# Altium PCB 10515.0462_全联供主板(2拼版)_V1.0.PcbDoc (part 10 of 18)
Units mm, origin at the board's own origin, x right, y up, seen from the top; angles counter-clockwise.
Board outline 282 x 198 mm, 2 copper layers (Top Layer, Bottom Layer); 716 components, 0 nets, 2364 pads, 1800 vias.
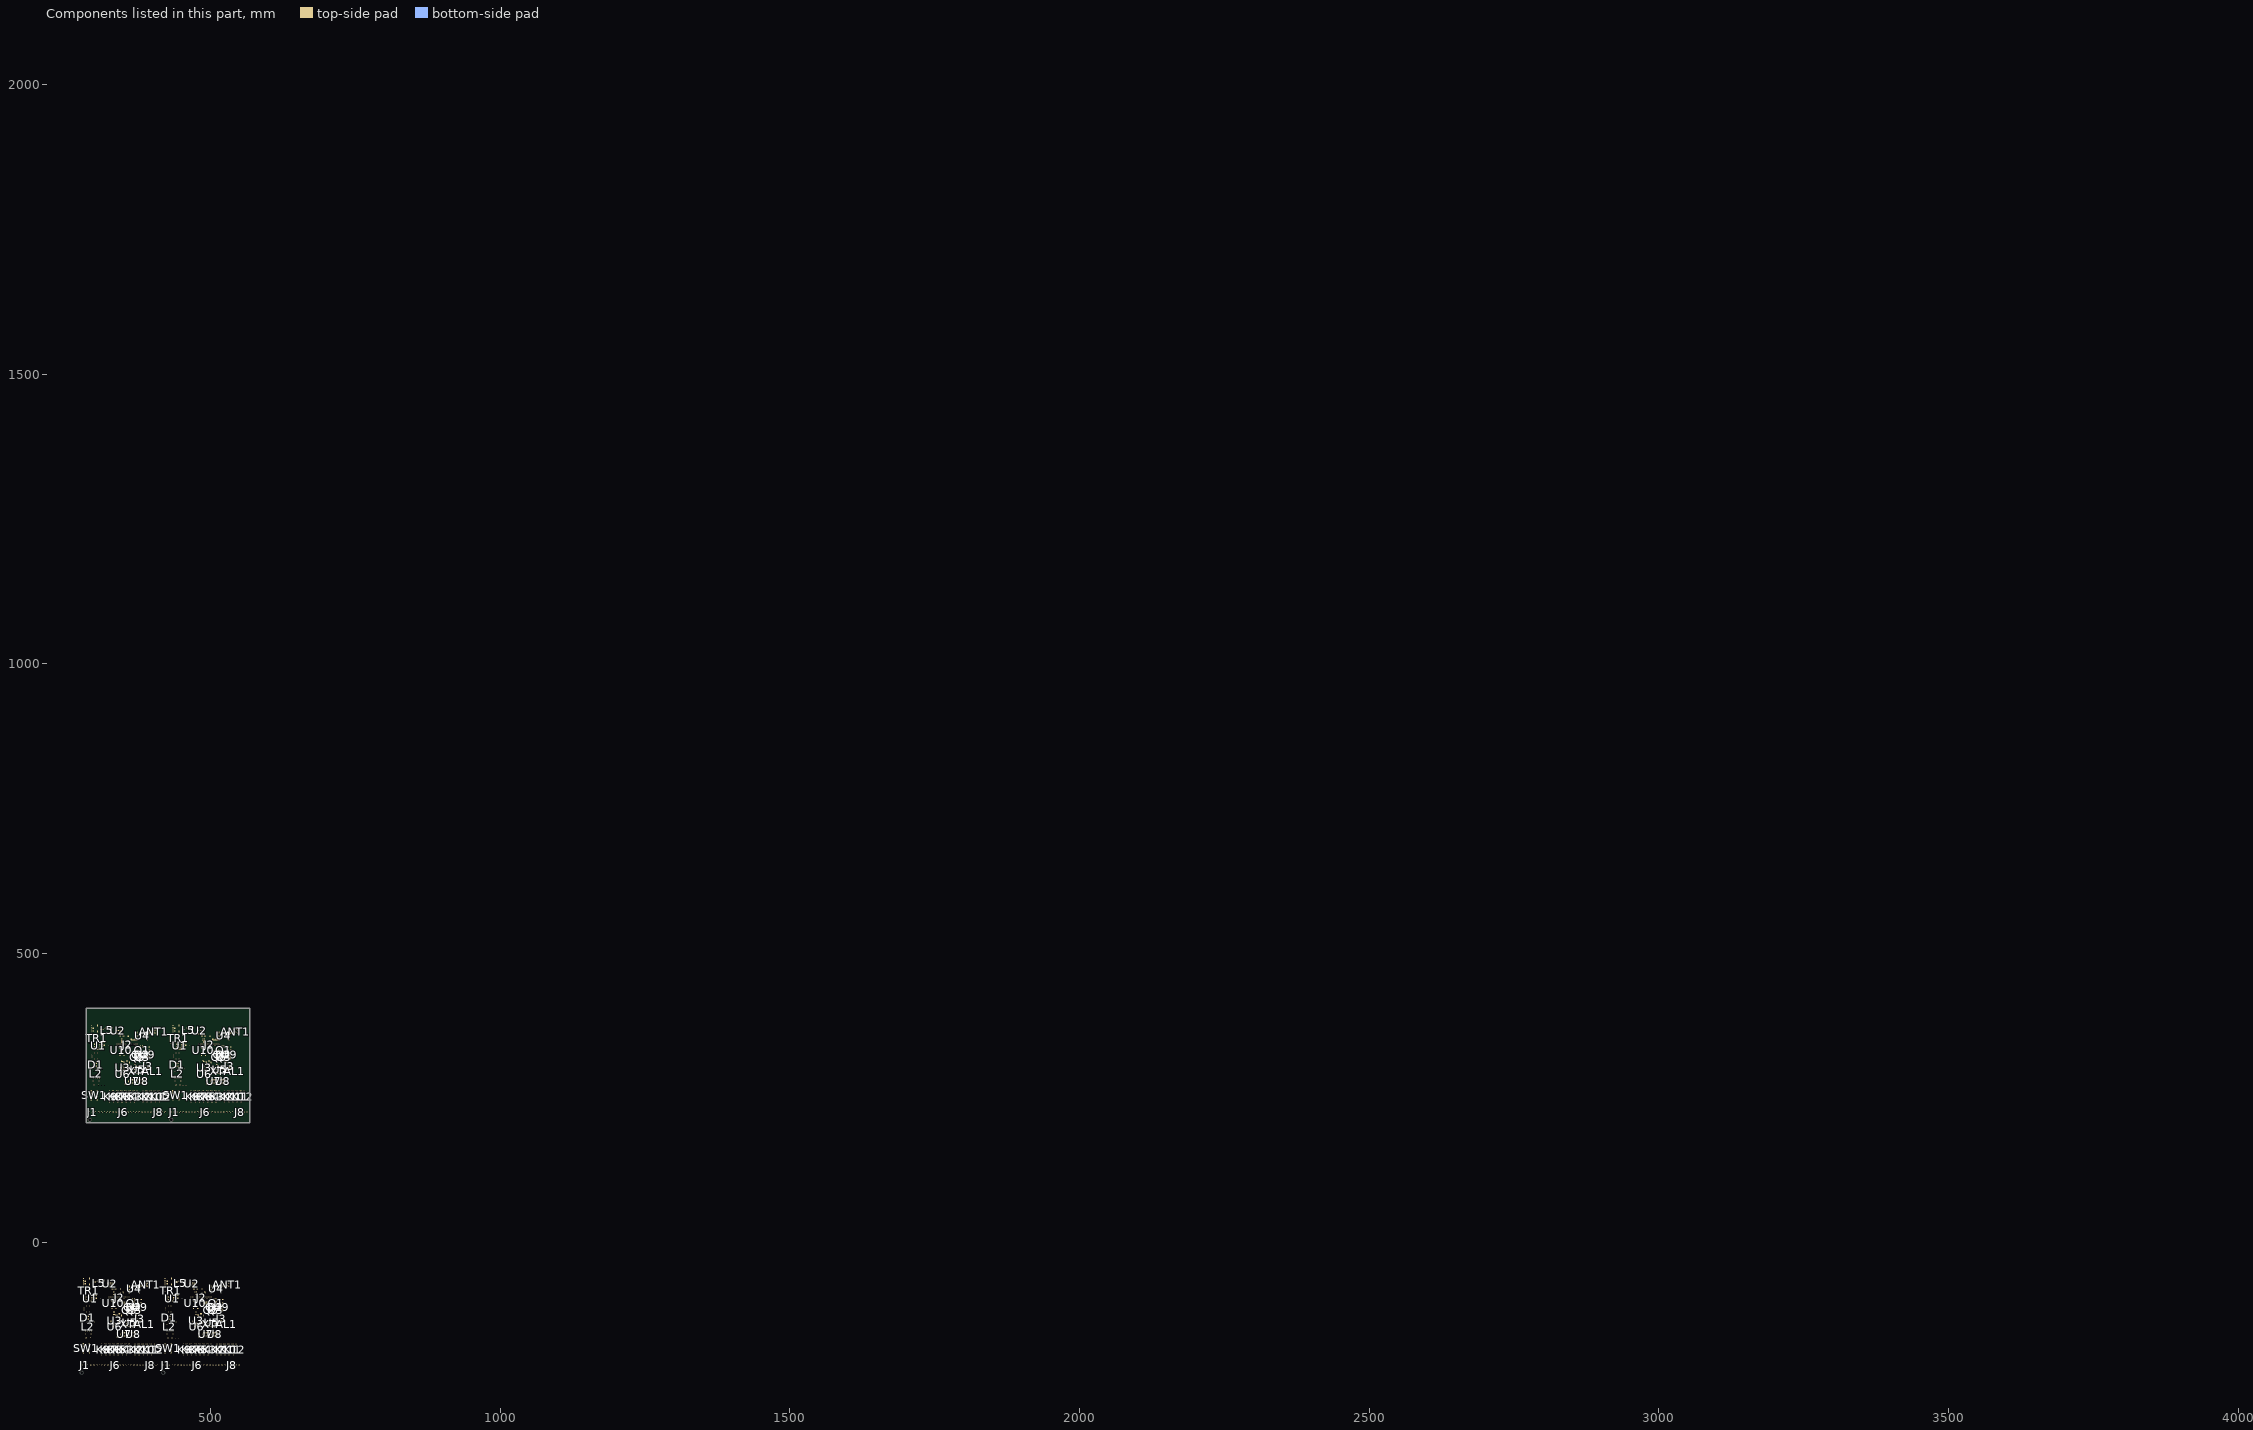
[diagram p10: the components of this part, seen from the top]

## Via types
v1: diameter 0.7, hole 0.4, Top Layer to Bottom Layer, tented both sides, 1800 vias

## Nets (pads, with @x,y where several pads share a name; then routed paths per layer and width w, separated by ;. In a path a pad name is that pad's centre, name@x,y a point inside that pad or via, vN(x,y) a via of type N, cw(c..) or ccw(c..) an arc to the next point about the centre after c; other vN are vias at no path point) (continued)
copper on no net: (continued)
  Top Layer w0.65: 372.479,328.689 cw(c371.859,328.069) 372.735,328.069 ; 372.735,317.501 cw(c374.744,317.501) 373.733,319.236 ; 372.735,317.686 372.735,318.663 373.577,319.504 ; 372.735,318.314 cw(c373.616,318.314) 373.587,319.194 ; 372.735,318.632 cw(c374.085,318.632) 373.406,319.798 ; 372.735,318.986 cw(c373.594,318.986) 373.566,319.844 ; 372.735,326.83 372.735,328.945 ; 372.735,327.857 cw(c373.911,327.857) 373.08,328.689 ; 372.76,322.137 v1(372.76,324.555) 372.76,325.393 ; v1(372.772,331.039) 372.772,332.937 ; 373.267,319.504 cw(c372.518,319.504) 373.048,318.975 cw(c373.577,318.446) 373.577,319.194 ; v1(373.614,-112.057) 374.453,-112.057 379.78,-112.057 380.616,-112.057 381.361,-112.802 381.361,-119.533 v1(381.615,-119.787) ; 374.386,317.686 376.545,317.686 376.545,316.965 376.956,316.554 v1(377.21,316.554) ; 374.386,326.83 374.386,323.814 374.577,323.624 374.577,322.004 ; 374.389,323.735 cw(c373.935,323.281) 374.577,323.281 ; 374.402,322.242 ccw(c373.982,322.663) 374.577,322.663 ccw(c375.172,322.663) 374.751,322.242 ; v1(375.457,-119.787) 375.457,-118.864 ; 375.908,329.29 ccw(c375.182,330.015) 376.208,330.015 ccw(c377.234,330.015) 376.509,329.29 ccw(c377.234,330.015) 377.234,328.989 ccw(c377.234,327.963) 376.509,328.689 ; 376.307,323.798 cw(c375.887,323.377) 376.482,323.377 cw(c377.077,323.377) 376.656,323.798 ; 376.359,331.324 cw(c377.972,329.711) 377.972,331.992 ; 376.482,322.068 376.482,324.036 ; 376.734,316.777 ccw(c377.21,317.253) v1@377.21,316.579 ; 377.003,-73.91 374.279,-73.91 373.36,-74.829 373.36,-83.465 372.695,-84.13 359.303,-84.13 357.866,-84.13 ; v1@377.006,-119.75 377.006,-118.864 ; 377.21,307.789 v1(377.21,309.315) ; 377.263,326.755 ccw(c376.733,327.284) 377.482,327.284 ccw(c378.23,327.284) 377.701,326.755 ; 377.482,326.536 377.482,328.846 ; 377.972,332.937 376.208,331.174 376.208,328.989 378.875,328.989 ; 378.196,319.845 378.196,317.686 380.482,317.686 ; 378.51,-108.253 378.51,-105.753 ; 378.51,-106.121 cw(c379.212,-106.121) 378.715,-105.624 ; 378.575,328.689 ccw(c377.849,327.963) 377.849,328.989 ccw(c377.849,330.015) 378.575,329.29 ; v1(378.92,308.486) 379.736,309.301 v1(379.736,310.331) ; v1(379.75,335.477) 380.829,335.477 ; 380.498,323.798 cw(c380.078,323.377) 380.673,323.377 cw(c381.268,323.377) 380.847,323.798 ; 380.673,324.036 380.673,322.964 381.673,321.964 384.252,321.964 384.356,322.068 ; 380.766,334.556 ccw(c381.641,334.556) 381.022,333.937 ; 380.766,335.477 380.766,333.781 380.848,333.699 ; 381.361,-119.113 ccw(c382.289,-119.113) v1@381.633,-119.769 ; 381.363,321.964 ccw(c380.614,321.964) 381.144,322.493 ccw(c381.673,323.022) 381.673,322.274 ; 381.579,330.98 cw(c379.827,329.229) 382.304,329.229 ; 381.798,331.2 382.304,330.693 382.304,328.989 ; 381.892,321.745 cw(c382.421,321.216) 382.421,321.964 cw(c382.421,322.712) 381.892,322.183 ; 382.004,329.29 ccw(c381.278,330.015) 382.304,330.015 ccw(c383.33,330.015) 382.605,329.29 ; 382.038,331.44 cw(c381.396,330.798) 382.304,330.798 ; 382.461,335.42 cw(c381.647,334.606) 382.798,334.606 ; 382.48,335.477 382.798,335.16 382.798,333.699 ; 382.623,319.464 382.623,319.143 v1(383.433,318.332) ; 382.624,333.937 ccw(c382.203,334.358) 382.798,334.358 ccw(c383.393,334.358) 382.972,333.937 ; v1@382.631,-74.482 385.033,-74.482 ; 382.869,319.401 ccw(c384.087,319.401) v1@383.226,318.539 ; v1@382.909,309.315 v1(382.909,309.442) 382.909,310.417 383.407,310.916 ; v1@382.909,309.396 cw(c384.633,309.396) 383.487,310.684 ; v1(387.243,324.539) 388.082,324.539 393.408,324.539 394.245,324.539 394.99,323.793 394.99,317.062 v1(395.244,316.808) ; v1(389.086,316.808) 389.086,317.731 ; 390.632,362.685 387.908,362.685 386.989,361.766 386.989,353.13 386.324,352.465 372.932,352.465 371.495,352.465 ; v1@390.634,316.846 390.634,317.731 ; 392.138,328.342 392.138,330.843 ; 392.138,330.475 cw(c392.841,330.475) 392.344,330.971 ; 394.99,317.482 ccw(c395.917,317.482) v1@395.262,316.826 ; v1@396.26,362.114 398.661,362.114 ; 426.476,-64.542 428.715,-64.542 431.89,-61.367 431.89,-62.336 436.122,-66.568 436.509,-66.568 ; 431.89,-71.667 431.89,-71.51 433.366,-70.035 ; 432.064,-69.749 433.614,-68.2 438.083,-68.2 437.55,-68.733 433.842,-68.733 433.461,-69.114 ; 432.318,-61.875 436.509,-66.066 437.601,-66.066 ; 432.318,-61.113 437.754,-66.549 437.837,-66.549 437.96,-66.426 ; 432.572,-70.003 433.144,-69.431 ; 433.017,-63.462 433.017,-64.288 ; 433.652,-64.923 433.017,-64.923 ; 434.35,-64.034 436.001,-65.685 437.22,-65.685 438.083,-66.549 ; 434.604,-66.568 434.604,-66.51 433.017,-64.923 ; 435.297,-66.568 433.017,-64.288 ; 436.691,-68.733 ccw(c436.691,-66.845) 438.026,-68.18 ; 436.813,-66.066 cw(c436.813,-67.78) 438.026,-66.568 436.509,-66.568 ; 438.083,-66.429 ccw(c438.083,-65.893) 438.462,-66.272 ; 438.141,-66.568 cw(c439.353,-67.78) 439.353,-66.066 ; 438.16,-68.479 437.208,-69.431 ; 438.164,-66.519 cw(c438.668,-66.573) 438.668,-66.066 ; 439.801,-66.565 ccw(c438.668,-67.601) 438.668,-66.066 ; 439.861,-66.549 439.379,-66.066 438.668,-66.066 ; 440.105,372.053 442.344,372.053 445.519,375.228 445.519,374.259 449.751,370.027 450.138,370.027 ; 440.738,-66.637 cw(c441.203,-67.102) 441.547,-66.542 ; 441.097,-65.669 cw(c442.224,-66.795) v1@442.224,-65.202 ; 441.272,-65.494 cw(c442.023,-66.246) v1@442.219,-65.202 ; 441.532,-66.415 ccw(c440.473,-65.356) v1@441.97,-65.356 ; v1@441.571,-65.195 cw(c440.609,-66.157) 441.97,-66.157 ; 441.589,-66.654 cw(c443.547,-66.654) v1@442.241,-65.196 ; 441.589,-66.391 ccw(c441.589,-65.336) 442.335,-66.082 ; v1@441.594,-65.202 cw(c441.79,-66.246) 442.542,-65.494 ; 441.612,-66.394 cw(c441.82,-65.685) 441.081,-65.685 ; 441.97,-65.851 cw(c442.898,-65.851) v1@442.242,-65.195 ; 441.995,-66.549 ccw(c441.995,-62.838) 444.619,-65.462 cw(c443.467,-64.309) 443.467,-65.939 cw(c443.467,-67.569) 444.619,-66.416 ; v1@442.206,-65.195 cw(c441.551,-65.851) 442.478,-65.851 ; 443.564,-66.549 ccw(c443.564,-64.407) 445.078,-65.921 ; 445.519,364.928 445.519,365.085 446.995,366.561 ; 445.693,366.846 447.242,368.396 451.712,368.396 451.178,367.862 447.471,367.862 447.09,367.481 ; 445.947,374.72 450.138,370.529 451.229,370.529 ; 445.947,375.482 451.382,370.047 451.466,370.047 451.589,370.17 ; 446.201,366.592 446.772,367.164 ; 446.645,373.133 446.645,372.307 ; 447.28,371.672 446.645,371.672 ; 447.979,372.561 449.63,370.91 450.848,370.91 451.712,370.047 ; 448.233,370.027 448.233,370.085 446.645,371.672 ; 448.925,370.027 446.645,372.307 ; 449.494,-66.416 cw(c448.342,-67.569) 449.971,-67.569 cw(c451.601,-67.569) 450.448,-66.416 ; 449.504,-73.001 ccw(c448.457,-71.908) 449.971,-71.908 ccw(c451.485,-71.908) 450.438,-73.001 ; 449.735,-66.571 cw(c449.266,-67.827) 450.606,-67.827 ; 449.962,-65.962 cw(c449.616,-66.89) 450.606,-66.89 ; 449.971,-66.614 cw(c449.971,-69.163) 451.774,-67.361 ; 449.996,-73.486 cw(c451.514,-73.292) 450.432,-72.209 ; 449.998,-72.815 ccw(c450.059,-71.234) 451.178,-72.353 ; 450.281,-72.889 cw(c450.941,-71.613) 449.504,-71.613 ; 450.32,367.862 ccw(c450.32,369.75) 451.654,368.415 ; 450.442,370.529 cw(c450.442,368.815) 451.654,370.027 450.138,370.027 ; 450.606,-67.082 451.368,-67.844 453.4,-67.844 ; 450.635,-66.059 ccw(c452.337,-66.367) 451.114,-67.59 ; 450.641,-73.403 cw(c453.174,-73.079) 451.368,-71.273 ; 450.646,-73.489 cw(c452.107,-73.489) 451.074,-72.456 ; 450.646,-65.939 ccw(c451.356,-65.939) 450.854,-66.441 ; 451.712,370.166 ccw(c451.712,370.702) 452.091,370.323 ; 451.769,370.027 cw(c452.982,368.815) 452.982,370.529 ; 451.789,368.116 450.836,367.164 ; 451.793,370.076 cw(c452.297,370.023) 452.297,370.529 ; 453.43,370.03 ccw(c452.297,368.995) 452.297,370.529 ; 453.49,370.047 453.007,370.529 452.297,370.529 ; 454.035,-68.479 455.813,-66.701 455.813,-66.574 ; 454.035,-67.844 454.035,-67.543 456.655,-64.923 ; 454.162,-67.844 455.813,-66.193 ; 454.257,-67.241 cw(c456.655,-69.64) 456.655,-66.248 ; 454.282,-66.581 cw(c456.655,-68.954) 456.655,-65.598 ; 454.289,-71.781 455.305,-72.797 455.305,-74.448 456.08,-75.223 456.655,-75.223 ; 454.367,369.958 cw(c454.832,369.493) 455.175,370.054 ; 454.393,-67.185 cw(c456.655,-69.447) 456.655,-66.248 ; 454.67,-67.844 453.4,-67.844 ; 454.71,370.91 ccw(c455.449,370.91) 455.241,370.201 ; 454.726,370.927 cw(c455.853,369.8) v1@455.853,371.393 ; 454.9,371.101 cw(c455.652,370.35) v1@455.848,371.394 ; 455.124,-66.882 cw(c456.655,-68.414) 456.655,-66.248 ; 455.16,370.181 ccw(c454.102,371.239) v1@455.599,371.239 ; v1@455.2,371.401 cw(c454.238,370.438) 455.599,370.438 ; 455.218,369.942 cw(c457.175,369.942) v1@455.87,371.4 ; 455.218,370.204 ccw(c455.218,371.259) 455.964,370.513 ; v1@455.223,371.394 cw(c455.419,370.35) 456.17,371.101 ; 455.366,-66.132 cw(c456.655,-67.421) 456.655,-65.598 ; 455.392,-65.471 cw(c456.655,-66.735) 456.655,-64.948 ; 455.432,-72.543 454.67,-71.781 451.749,-71.781 451.178,-72.352 ; 455.503,-66.075 cw(c456.655,-67.228) 456.655,-65.598 ; 455.599,370.745 cw(c456.526,370.745) v1@455.871,371.401 ; 455.624,370.047 ccw(c455.624,373.758) 458.248,371.134 cw(c457.095,372.286) 457.095,370.656 cw(c457.095,369.027) 458.248,370.179 ; 455.663,-66.851 ccw(c454.534,-65.723) 456.13,-65.723 ; 455.813,-74.261 ccw(c456.817,-74.261) 456.107,-74.971 ; 455.813,-72.692 ccw(c458.386,-72.692) 456.567,-74.511 ; 455.813,-72.289 454.797,-71.273 451.368,-71.273 449.971,-72.67 449.971,-73.489 ; 455.813,-71.527 455.051,-70.765 451.114,-70.765 449.971,-71.908 449.971,-73.489 ; 455.813,-71.123 ccw(c459.955,-71.123) 457.026,-74.052 cw(c457.923,-73.156) 456.655,-73.156 cw(c455.388,-73.156) 456.284,-74.052 ; 455.813,-68.123 cw(c458.079,-68.123) 456.923,-66.175 ; 455.813,-67.971 454.924,-68.86 ; 455.813,-67.336 454.67,-68.479 451.368,-68.479 450.606,-67.717 450.606,-66.574 449.971,-65.939 ; 455.813,-66.982 cw(c457.402,-66.982) 456.591,-65.615 ; v1@455.835,371.401 cw(c455.179,370.745) 456.107,370.745 ; 455.881,-66.633 ccw(c455.226,-65.978) 456.138,-65.815 ; 455.94,-64.923 453.527,-67.336 451.749,-67.336 450.352,-65.939 449.971,-65.939 ; 456.284,-75.594 ccw(c455.388,-76.49) 455.388,-75.223 ccw(c455.388,-73.956) 456.284,-74.852 ; 456.321,-75.223 455.318,-75.223 454.924,-74.829 454.924,-73.305 453.972,-72.352 451.178,-72.352 ; 456.325,-74.015 ccw(c454.829,-72.162) 457.21,-72.162 ; 456.465,-73.934 ccw(c455.827,-72.289) 457.591,-72.289 ; 456.578,-74.522 ccw(c457.044,-73.925) 457.579,-74.46 ; 456.655,-65.859 456.655,-64.923 ; 456.7,-74.54 ccw(c456.196,-73.238) 457.591,-73.238 ; 456.734,-74.52 ccw(c455.928,-73.523) 457.21,-73.523 ; 456.935,-75.146 ccw(c456.564,-74.188) 457.591,-74.188 ; 456.978,-74.009 ccw(c457.5,-73.34) 458.099,-73.94 ; 457.026,-66.094 ccw(c457.923,-66.99) 456.655,-66.99 ccw(c455.388,-66.99) 456.284,-66.094 cw(c454.354,-68.024) 457.083,-68.024 ; 457.106,-75.491 cw(c457.578,-75.772) 457.578,-75.223 ; 457.106,-74.955 ccw(c457.578,-74.674) 457.578,-75.223 ; 457.18,-65.723 ccw(c459.162,-65.723) 457.761,-67.125 ; 457.193,370.047 ccw(c457.193,372.189) 458.707,370.674 ; 458.353,-71.527 457.591,-72.289 457.591,-74.575 456.943,-75.223 456.655,-75.223 ; 458.516,-68.733 cw(c458.516,-70.094) v1@459.478,-69.132 ; 458.933,-69.278 ccw(c458.933,-67.609) v1@460.113,-68.789 ; 458.988,-71.527 458.099,-72.416 458.099,-73.94 ; 459.04,-69.278 ccw(c459.04,-68.658) v1@459.478,-69.096 ; 459.274,-68.638 cw(c458.798,-69.114) v1@459.471,-69.114 ; v1@459.514,-69.132 cw(c460.476,-70.094) 460.476,-68.733 ; v1@459.514,-69.096 ccw(c459.952,-68.658) 459.952,-69.278 ; v1@459.517,-69.128 cw(c460.131,-69.554) v1(460.131,-68.807) 459.443,-68.807 457.083,-66.447 ; 459.517,-68.733 cw(c459.517,-70.653) v1@460.875,-69.295 ; v1@460.154,-68.797 ccw(c460.893,-68.47) v1(460.893,-69.278) ; 460.675,-68.733 cw(c460.675,-70.094) v1@461.637,-69.132 ; v1@460.915,-69.29 cw(c461.872,-69.834) 461.872,-68.733 ; v1@461.199,-69.278 ccw(c461.199,-68.658) v1@461.637,-69.096 ; 461.285,-71.527 ccw(c461.285,-69.418) 462.776,-70.909 ; v1@461.673,-69.096 ccw(c462.111,-68.658) 462.111,-69.278 ; 461.909,-72.416 461.655,-72.162 ; 461.909,-71.867 462.834,-70.942 ; 462.1,-68.961 ccw(c462.635,-68.425) 462.815,-69.161 ; 462.157,-70.809 ccw(c462.48,-70.486) 462.78,-70.829 ; 462.29,-70.942 461.859,-70.511 457.464,-70.511 456.655,-71.32 456.655,-72.543 ; 462.417,-69.278 461.872,-68.733 ; 462.753,-72.67 462.753,-72.031 462.249,-71.527 ; 462.834,-70.929 462.834,-70.942 ; 462.834,-69.278 v1(460.893,-69.278) ; 462.847,-70.942 462.834,-70.942 ; 463.123,370.179 cw(c461.97,369.027) 463.6,369.027 cw(c465.229,369.027) 464.077,370.179 ; 463.133,363.594 ccw(c462.086,364.687) 463.6,364.687 ccw(c465.114,364.687) 464.067,363.594 ; 463.364,370.024 cw(c462.894,368.769) 464.235,368.769 ; 463.484,-73.99 463.243,-73.749 ; 463.525,-73.441 462.036,-71.953 462.036,-71.527 ; 463.591,370.633 cw(c463.244,369.705) 464.235,369.705 ; 463.6,369.981 cw(c463.6,367.432) 465.403,369.235 ; 463.625,363.11 cw(c465.143,363.304) 464.061,364.386 ; 463.626,363.781 ccw(c463.688,365.361) 464.806,364.243 ; 463.91,363.706 cw(c464.57,364.983) 463.133,364.983 ; 464.235,369.513 464.997,368.751 467.029,368.751 ; 464.264,370.536 ccw(c465.965,370.228) 464.743,369.006 ; 464.269,363.192 cw(c466.803,363.516) 464.997,365.322 ; 464.275,363.106 cw(c465.735,363.106) 464.703,364.139 ; 464.275,370.656 ccw(c464.985,370.656) 464.483,370.155 ; 465.272,-96.104 cw(c464.526,-96.85) 465.581,-96.85 cw(c466.636,-96.85) 465.89,-96.104 cw(c466.636,-96.85) 466.636,-95.795 cw(c466.636,-94.74) 465.89,-95.486 cw(c466.636,-94.74) 465.581,-94.74 cw(c464.526,-94.74) 465.272,-95.486 ; 465.272,-93.564 cw(c464.526,-94.31) 465.581,-94.31 cw(c466.636,-94.31) 465.89,-93.564 cw(c466.664,-94.338) 466.664,-93.244 ; 465.369,-95.413 ccw(c464.799,-94.387) 465.973,-94.387 ; 465.4,-95.683 cw(c466.821,-96.57) 466.821,-94.895 ; 465.427,-93.664 cw(c465.131,-94.453) 465.973,-94.453 ; 465.43,-93.405 ccw(c466.564,-92.283) 466.564,-93.879 ; 465.468,-95.976 ccw(c465.926,-95.242) 466.538,-95.854 ; 465.592,-93.244 468.11,-93.244 468.121,-93.255 ; 465.812,-95.425 ccw(c466.371,-94.531) 467.116,-95.276 ; 465.89,-92.946 ccw(c466.608,-92.228) 466.608,-93.244 ; 465.892,-92.948 ccw(c468.121,-90.744) 468.121,-93.879 ; 465.952,-96.027 cw(c467.994,-97.303) 467.994,-94.895 465.973,-94.895 ; 465.973,-96.419 467.116,-95.276 ; 465.973,-96.188 465.973,-94.895 ; 465.973,-95.988 cw(c467.116,-96.549) 467.116,-95.276 ; 467.017,-94.895 cw(c467.017,-96.338) 468.312,-95.701 ; 467.038,-93.244 cw(c467.038,-94.338) 467.812,-93.564 cw(c467.066,-94.31) 468.121,-94.31 cw(c469.176,-94.31) 468.43,-93.564 ; 467.094,-93.244 ccw(c467.094,-92.228) 467.812,-92.946 ; 467.379,-93.879 ccw(c467.379,-92.79) 468.301,-93.369 ; 467.664,368.116 469.442,369.894 469.442,370.021 ; 467.664,368.751 467.664,369.052 470.284,371.672 ; 467.685,-95.817 ccw(c467.116,-95.845) 467.116,-95.276 ; 467.729,-95.988 ccw(c465.973,-96.851) 465.973,-94.895 ; 467.751,-93.023 cw(c466.205,-92.054) 466.205,-93.879 468.121,-93.879 ; 467.791,368.751 469.442,370.402 ; 467.812,-96.104 ccw(c467.066,-96.85) 467.066,-95.795 ccw(c467.066,-94.74) 467.812,-95.486 ccw(c467.066,-94.74) 468.121,-94.74 ccw(c469.176,-94.74) 468.43,-95.486 ; 467.885,369.354 cw(c470.284,366.956) 470.284,370.347 ; 467.911,370.015 cw(c470.284,367.642) 470.284,370.997 ; 467.918,364.814 468.934,363.798 468.934,362.147 469.709,361.372 470.284,361.372 ; 468.022,369.411 cw(c470.284,367.149) 470.284,370.347 ; 468.121,-95.276 467.116,-95.276 ; 468.121,-94.387 465.973,-94.387 ; 468.299,368.751 467.029,368.751 ; 468.753,369.713 cw(c470.284,368.182) 470.284,370.347 ; 468.995,370.464 cw(c470.284,369.175) 470.284,370.997 ; 469.021,371.124 cw(c470.284,369.861) 470.284,371.647 ; 469.061,364.052 468.299,364.814 465.378,364.814 464.806,364.243 ; 469.132,370.52 cw(c470.284,369.368) 470.284,370.997 ; 469.291,369.744 ccw(c468.163,370.872) 469.759,370.872 ; 469.442,362.334 ccw(c470.446,362.334) 469.736,361.624 ; 469.442,363.903 ccw(c472.015,363.903) 470.195,362.084 ; 469.442,364.306 468.426,365.322 464.997,365.322 463.6,363.925 463.6,363.106 ; 469.442,365.068 468.68,365.83 464.743,365.83 463.6,364.687 463.6,363.106 ; 469.442,365.473 ccw(c473.584,365.473) 470.655,362.544 cw(c471.551,363.44) 470.284,363.44 cw(c469.016,363.44) 469.913,362.544 ; 469.442,368.472 cw(c471.708,368.472) 470.552,370.421 ; 469.442,368.624 468.553,367.735 ; 469.442,369.259 468.299,368.116 464.997,368.116 464.235,368.878 464.235,370.021 463.6,370.656 ; 469.442,369.613 cw(c471.031,369.613) 470.22,370.98 ; 469.51,369.963 ccw(c468.855,370.618) 469.767,370.78 ; 469.569,371.672 467.156,369.259 465.378,369.259 463.981,370.656 463.6,370.656 ; 469.913,361.001 ccw(c469.016,360.105) 469.016,361.372 ccw(c469.016,362.64) 469.913,361.744 ; 469.95,361.372 468.947,361.372 468.553,361.766 468.553,363.29 467.6,364.243 464.806,364.243 ; 469.954,362.581 ccw(c468.457,364.433) 470.839,364.433 ; 470.094,362.662 ccw(c469.456,364.306) 471.22,364.306 ; 470.207,362.074 ccw(c470.673,362.671) 471.208,362.136 ; 470.284,370.736 470.284,371.672 ; 470.329,362.056 ccw(c469.824,363.357) 471.22,363.357 ; 470.352,-95.486 ccw(c469.606,-94.74) 470.661,-94.74 ccw(c471.716,-94.74) 470.97,-95.486 ; 470.352,-93.564 cw(c469.606,-94.31) 470.661,-94.31 cw(c471.716,-94.31) 470.97,-93.564 ; 470.352,-92.946 ccw(c469.606,-92.2) 470.661,-92.2 ccw(c471.716,-92.2) 470.97,-92.946 ; 470.362,362.075 ccw(c469.557,363.073) 470.839,363.073 ; 470.474,-113.477 cw(c470.474,-114.971) 471.531,-113.915 ; 470.499,-112.8 ccw(c471.612,-112.7) 471.612,-113.818 ; 470.529,-113.475 cw(c470.601,-114.341) 471.216,-113.726 cw(c471.633,-113.309) 471.092,-113.073 ; 470.535,-113.474 cw(c470.633,-114.563) 471.406,-113.79 cw(c472.093,-113.103) 471.138,-112.925 ; 470.564,361.45 ccw(c470.193,362.408) 471.22,362.408 ; 470.607,362.586 ccw(c471.128,363.255) 471.728,362.655 ; 470.655,370.501 ccw(c471.551,369.605) 470.284,369.605 ccw(c469.016,369.605) 469.913,370.501 cw(c467.983,368.572) 470.712,368.572 ; 470.661,-100.366 470.661,-95.795 ; 470.661,-99.135 ccw(c471.596,-99.135) 470.935,-99.796 ; 470.735,361.104 cw(c471.207,360.824) 471.207,361.372 ; 470.735,361.641 ccw(c471.207,361.921) 471.207,361.372 ; 470.776,-100.481 470.776,-95.91 470.661,-95.795 ; 470.776,-97.128 ccw(c469.329,-97.128) 470.352,-96.104 cw(c469.606,-96.85) 470.661,-96.85 cw(c471.716,-96.85) 470.97,-96.104 ccw(c471.439,-96.573) 470.776,-96.573 ; 470.809,370.872 ccw(c472.791,370.872) 471.389,369.471 ; 470.951,-113.279 cw(c472.104,-114.432) 472.104,-112.802 cw(c472.104,-111.172) 470.951,-112.325 ; 471.12,-112.998 cw(c472.069,-113.286) 472.069,-112.294 ; 471.146,-112.742 ccw(c472.323,-112.637) 472.323,-113.818 ; 471.149,-112.802 ccw(c472.914,-112.802) 471.666,-114.05 ; 471.434,-113.818 472.831,-115.215 472.831,-118.39 473.238,-118.796 473.238,-119.329 ; 471.982,365.068 471.22,364.306 471.22,362.02 470.572,361.372 470.284,361.372 ; 472.021,-106.75 ccw(c470.37,-105.1) 472.704,-105.1 ; 472.145,367.862 cw(c472.145,366.501) v1@473.107,367.464 ; 472.531,-121.612 cw(c470.824,-123.318) 473.238,-123.318 ; 472.531,-121.01 ccw(c470.824,-119.304) 473.238,-119.304 ; 472.562,367.318 ccw(c472.562,368.987) v1@473.742,367.807 ; 472.617,365.068 471.728,364.179 471.728,362.655 ; 472.669,367.318 ccw(c472.669,367.937) v1@473.107,367.499 ; 472.695,-107.811 cw(c471.415,-109.091) 473.226,-109.091 cw(c475.036,-109.091) 473.756,-107.811 ; 472.695,-106.75 ccw(c471.777,-105.832) 473.076,-105.832 ; 472.704,-107.802 472.704,-108.865 ; 472.704,-105.84 ccw(c473.991,-105.84) 473.081,-106.75 ; 472.704,-102.446 cw(c474.516,-102.446) 473.235,-101.165 ; 472.704,-98.515 ccw(c474.516,-98.515) 473.235,-99.796 ; 472.704,-98.05 cw(c475.456,-98.05) 473.51,-96.104 ccw(c474.558,-97.153) 473.076,-97.153 ; 472.704,-96.481 cw(c473.886,-96.481) 473.05,-95.645 ; 472.704,-95.51 cw(c475.456,-95.51) 473.51,-93.564 ccw(c474.256,-94.31) 473.201,-94.31 ccw(c472.146,-94.31) 472.892,-93.564 ; 472.704,-95.174 ccw(c473.738,-95.174) 473.062,-95.956 ; 472.704,-93.941 cw(c473.886,-93.941) 473.05,-93.105 ; 472.812,-91.231 ccw(c472.063,-90.481) 473.118,-90.381 ; 472.881,-87.133 cw(c472.019,-87.995) 473.238,-87.995 ; 472.892,-96.104 cw(c472.448,-96.548) 473.076,-96.548 ; 472.892,-95.486 ccw(c472.146,-94.74) 473.201,-94.74 ccw(c474.256,-94.74) 473.51,-95.486 ; 472.903,367.958 cw(c472.426,367.481) v1@473.1,367.481 ; 473.076,-107.131 473.076,-100.481 473.076,-95.921 ; 473.076,-105.108 ccw(c475.399,-105.108) 473.756,-106.75 ; 473.076,-104.792 473.847,-105.563 473.847,-111.278 473.226,-111.899 ; v1@473.143,367.464 cw(c474.105,366.501) 474.105,367.862 ; v1@473.143,367.499 ccw(c473.581,367.937) 473.581,367.318 ; v1@473.145,367.467 cw(c473.76,367.041) v1(473.76,367.789) 473.072,367.789 470.712,370.148 ; 473.146,367.862 cw(c473.146,365.942) v1@474.504,367.3 ; 473.201,-95.795 473.201,-93.255 472.704,-93.752 ; 473.218,-123.451 cw(c472.313,-124.356) 473.593,-124.356 ; 473.226,-107.281 473.226,-111.899 ; 473.228,-123.459 cw(c472.713,-124.173) 473.593,-124.173 ; 473.238,-86.939 473.238,-88.849 473.238,-90.806 472.577,-91.466 471.18,-91.466 470.661,-91.985 470.661,-93.255 470.661,-95.795 ; 473.344,-123.437 ccw(c473.663,-123.64) 473.396,-123.908 ; 473.37,-107.811 cw(c472.22,-108.962) 473.847,-108.962 ; 473.37,-106.75 ccw(c472.22,-105.6) 473.847,-105.6 ; 473.429,-130.582 cw(c473.429,-131.948) 474.395,-130.982 ; 473.487,-95.465 cw(c474.969,-93.752) 472.704,-93.752 ; 473.593,-125.629 473.593,-125.248 ; v1@473.783,367.799 ccw(c474.522,368.126) v1(474.522,367.318) ; 473.847,-109.221 cw(c475.841,-109.221) 474.431,-107.811 ; 473.847,-105.563 ccw(c475.334,-105.563) 474.381,-106.705 ; 474.304,367.862 cw(c474.304,366.501) v1@475.266,367.464 ; 474.355,-125.985 473.619,-125.248 473.593,-125.248 ; 474.371,-130.926 ccw(c474.021,-130.932) 474.021,-130.582 ; 474.491,-131.051 474.021,-130.582 ; v1@474.544,367.305 cw(c475.501,366.761) 475.501,367.862 ; v1@474.828,367.318 ccw(c474.828,367.937) v1@475.266,367.499 ; 474.869,-119.387 cw(c473.657,-120.599) 475.371,-120.599 ; 474.869,-88.791 ccw(c473.681,-87.604) 475.361,-87.604 ; 474.889,-91.11 475.741,-91.963 475.741,-93.255 ; 474.889,-88.744 cw(c477.166,-88.744) 475.556,-87.133 ccw(c476.025,-87.603) 475.361,-87.603 ; 474.909,-119.408 cw(c474.78,-119.985) 475.371,-119.985 ; 474.914,365.068 ccw(c474.914,367.177) 476.405,365.686 ; 475.008,-123.389 cw(c476.251,-123.334) 475.371,-122.454 ; 475.008,-119.329 cw(c476.092,-119.329) 475.325,-118.563 ; 475.167,-87.133 cw(c474.697,-87.603) 475.361,-87.603 ; 475.217,-101.165 cw(c473.311,-103.07) 476.006,-103.07 ; 475.217,-99.796 ccw(c473.311,-97.891) 476.006,-97.891 ; 475.244,-99.97 475.244,-95.022 ; 475.244,-99.094 ccw(c476.237,-99.094) 475.535,-99.796 ; 475.244,-98.05 cw(c477.996,-98.05) 476.05,-96.104 ; 475.244,-96.481 cw(c476.426,-96.481) 475.59,-95.645 ; 475.244,-95.11 ccw(c476.426,-95.11) 475.59,-95.946 ; 475.244,-95.09 cw(c477.077,-95.09) 475.998,-93.609 ; 475.244,-93.541 ccw(c477.996,-93.541) 476.05,-95.486 ; v1@475.302,367.499 ccw(c475.74,367.937) 475.74,367.318 ; 475.376,-101.231 cw(c475.376,-103.024) 476.644,-101.756 ; 475.376,-97.732 cw(c477.678,-97.732) 476.05,-96.104 ; 475.376,-96.161 475.376,-100.481 475.376,-103.663 476.006,-104.293 ; 475.422,-123.926 ccw(c476.068,-123.279) 476.633,-123.999 ; 475.432,-96.104 cw(c474.046,-97.49) 476.006,-97.49 ; 475.432,-95.486 ccw(c474.686,-94.74) 475.741,-94.74 ccw(c476.796,-94.74) 476.05,-95.486 ; 475.432,-93.564 cw(c474.686,-94.31) 475.741,-94.31 cw(c476.796,-94.31) 476.05,-93.564 cw(c476.796,-94.31) 476.796,-93.255 cw(c476.796,-92.2) 476.05,-92.946 ; 475.432,-92.946 ccw(c474.686,-92.2) 475.741,-92.2 ccw(c476.796,-92.2) 476.05,-92.946 ; 475.46,-101.214 cw(c475.74,-101.902) 476.265,-101.377 ; 475.538,364.179 475.284,364.433 ; 475.538,364.728 476.463,365.653 ; 475.562,-93.371 ccw(c476.961,-92.468) 476.961,-94.133 ; 475.57,-95.668 cw(c476.858,-96.629) 476.858,-95.022 ; 475.576,-113.613 cw(c477.474,-115.512) 477.474,-112.827 ; 475.586,-95.942 ccw(c476.4,-95.171) 476.4,-96.292 ; 475.676,-100.705 cw(c474.88,-101.501) 476.006,-101.501 ; 475.676,-100.256 ccw(c474.88,-99.46) 476.006,-99.46 ; 475.729,367.635 ccw(c476.264,368.17) 476.443,367.435 ; 475.767,-114.184 cw(c477.474,-115.891) 477.474,-113.477 ; 475.785,365.787 ccw(c476.108,366.11) 476.409,365.766 ; 475.829,-124.334 474.889,-123.393 ; 475.832,-92.828 cw(c475.988,-92.101) 475.244,-92.101 ; 475.844,-113.345 cw(c476.455,-113.957) 477.028,-113.308 ; 475.879,-92.736 477.403,-92.736 ; 475.919,365.653 475.488,366.084 471.093,366.084 470.284,365.275 470.284,364.052 ; 475.94,-124.445 ccw(c476.524,-123.861) 477.034,-124.511 ; 476.006,-104.471 cw(c476.868,-104.471) v1@476.524,-103.681 ; 476.006,-102.371 ccw(c477.801,-102.371) v1@476.532,-103.64 ; 476.006,-101.118 476.514,-101.626 476.514,-111.024 477.474,-111.984 477.474,-112.802 ; 476.006,-96.927 476.641,-96.292 477.911,-96.292 ; 476.006,-96.061 476.006,-104.293 ; 476.046,367.318 475.501,367.862 ; 476.058,-95.495 ccw(c477.911,-93.74) 477.911,-96.292 ; 476.091,-96.057 cw(c478.154,-97.595) 478.154,-95.022 475.244,-95.022 ; 476.108,-93.018 ccw(c478.154,-91.698) 478.154,-94.133 475.741,-94.133 ; 476.119,-93.475 cw(c477.403,-94.221) 477.403,-92.736 ; 476.142,-131.051 476.142,-130.082 475.371,-129.312 466.989,-129.312 466.227,-129.312 465.581,-128.666 465.581,-95.795 ; 476.333,-112.856 cw(c476.914,-113.437) 477.458,-112.821 ; 476.382,363.925 476.382,364.565 475.878,365.068 ; 476.463,365.667 476.463,365.653 ; 476.463,367.318 v1(474.522,367.318) ; 476.476,365.653 476.463,365.653 ; 476.552,-113.399 ccw(c475.954,-112.802) 476.799,-112.802 ccw(c475.17,-112.802) 476.322,-111.65 ccw(c477.474,-110.497) 477.474,-112.127 ; 476.595,-124.634 ccw(c475.869,-125.36) 475.869,-124.334 ccw(c475.869,-123.308) 476.595,-124.033 ; 476.869,-113.101 ccw(c476.387,-113.34) 476.387,-112.802 ; 476.869,-112.503 cw(c476.387,-112.264) 476.387,-112.802 ; 477.027,-111.537 cw(c475.973,-112.591) 477.449,-112.799 ; 477.112,362.605 476.871,362.846 ; 477.149,-112.802 475.371,-114.58 475.371,-118.517 474.889,-119 474.889,-119.329 475.371,-119.812 475.371,-122.454 474.889,-122.937 474.889,-123.393 ; 477.153,363.154 475.665,364.642 475.665,365.068 ; 477.196,-124.634 cw(c477.921,-125.36) 477.921,-124.334 cw(c477.921,-123.308) 477.196,-124.033 ; 477.292,-96.292 ccw(c477.292,-95.069) 478.157,-95.934 ; 477.403,-93.128 477.403,-92.736 ; 477.544,-95.403 cw(c477.544,-96.27) 478.157,-95.657 ; 477.599,-93.625 ccw(c477.599,-92.835) 478.157,-93.394 ; 477.688,-93.625 cw(c477.688,-91.308) 476.05,-92.946 ; 477.743,-95.403 ccw(c477.743,-97.797) 476.05,-96.104 ; 477.784,-93.128 477.784,-88.164 ; 477.784,-91.371 ccw(c479.903,-91.371) 478.405,-92.87 ; 478.281,-95.403 476.133,-95.403 475.741,-95.795 ; 478.281,-94.641 475.741,-94.641 ; 478.281,-93.625 476.111,-93.625 475.741,-93.255 ; 478.281,-89.445 483.654,-84.072 483.654,-83.183 ; 478.281,-88.556 478.281,-93.255 ; 478.399,-87.402 483.236,-82.565 ; 478.901,340.491 cw(c478.155,339.745) 479.21,339.745 cw(c480.265,339.745) 479.519,340.491 cw(c480.265,339.745) 480.265,340.8 cw(c480.265,341.855) 479.519,341.109 cw(c480.265,341.855) 479.21,341.855 cw(c478.155,341.855) 478.901,341.109 ; 478.901,343.031 cw(c478.155,342.285) 479.21,342.285 cw(c480.265,342.285) 479.519,343.031 cw(c480.292,342.257) 480.292,343.351 ; 478.977,-126.104 cw(c478.977,-127.437) 479.92,-126.494 ; 478.978,-124.214 ccw(c478.992,-123.408) 479.562,-123.978 ; 478.998,341.182 ccw(c478.428,342.208) 479.602,342.208 ; 479.009,-126.098 cw(c479.237,-126.628) 479.645,-126.22 ; 479.029,340.913 cw(c480.45,340.025) 480.45,341.7 ; 479.035,-124.353 cw(c479.94,-125.259) 479.94,-123.978 ; 479.053,-124.325 cw(c479.562,-124.525) 479.562,-123.978 ; 479.056,342.931 cw(c478.759,342.143) 479.602,342.143 ; 479.058,343.19 ccw(c480.193,344.312) 480.193,342.716 ; 479.097,340.619 ccw(c479.555,341.353) 480.167,340.741 ; 479.221,343.351 481.738,343.351 481.75,343.34 ; 479.441,341.171 ccw(c480,342.065) 480.745,341.319 ; 479.519,343.649 ccw(c480.237,344.368) 480.237,343.351 ; 479.521,343.647 ccw(c481.75,345.851) 481.75,342.716 ; 479.58,340.568 cw(c481.623,339.292) 481.623,341.7 ; 479.602,340.176 480.745,341.319 ; 479.602,340.408 479.602,341.7 ; 479.602,340.607 cw(c480.745,340.046) 480.745,341.319 ; 480.636,-127.211 ccw(c481.396,-126.45) 482.028,-127.321 ; 480.646,341.7 cw(c480.646,340.257) 481.941,340.894 ; 480.667,343.351 cw(c480.667,342.257) 481.441,343.031 cw(c480.695,342.285) 481.75,342.285 cw(c482.805,342.285) 482.059,343.031 ; 480.722,343.351 ccw(c480.722,344.368) 481.441,343.649 ; 481.008,342.716 ccw(c481.008,343.805) 481.93,343.227 ; 481.144,-127.211 ccw(c481.655,-126.699) 482.053,-127.304 ; 481.175,-127.749 ccw(c481.849,-127.075) 482.409,-127.847 ; 481.257,-123.426 cw(c482.424,-124.592) 482.424,-122.943 ; 481.278,-123.406 ccw(c480.14,-122.268) 481.749,-122.268 ; 481.313,340.778 ccw(c480.745,340.75) 480.745,341.319 ; 481.358,340.607 ccw(c479.602,339.744) 479.602,341.7 ; 481.379,343.572 cw(c479.833,344.541) 479.833,342.716 481.75,342.716 481.75,343.34 ; 481.441,340.491 ccw(c480.695,339.745) 480.695,340.8 ccw(c480.695,341.855) 481.441,341.109 ccw(c480.695,341.855) 481.75,341.855 ccw(c482.805,341.855) 482.059,341.109 ; 481.531,-126.454 479.88,-126.454 ; 481.623,341.7 479.602,341.7 ; 481.75,341.319 480.745,341.319 ; 481.75,342.208 479.602,342.208 ; 481.801,-127.608 cw(c481.34,-127.416) 481.34,-127.915 ; 481.838,-128.204 ccw(c481.34,-128.49) 481.34,-127.915 ; 481.839,-123.603 ccw(c481.349,-123.113) 481.893,-122.685 ; 481.848,-127.915 480.832,-126.899 480.832,-126.645 ; v1@481.902,-88.11 cw(c483.245,-89.454) v1@483.245,-87.554 ; 481.951,-126.645 480.832,-126.645 ; 481.956,-126.118 cw(c480.711,-127.363) 482.4,-127.861 ; 482.416,-122.268 480.705,-123.978 480.578,-123.978 ; v1@482.42,-87.466 ccw(c482.849,-87.036) v1@483.229,-87.51 ; 482.474,-81.442 cw(c485.023,-83.99) 485.023,-80.386 ccw(c485.023,-82.016) 483.871,-80.863 ccw(c482.719,-79.711) 484.348,-79.711 ; v1@482.499,-88.31 cw(c482.879,-88.784) v1@483.309,-88.354 ; v1@482.501,-88.309 cw(c483.31,-89.118) v1@483.31,-87.973 ; v1@482.501,-87.511 cw(c484.492,-89.502) 485.018,-86.736 ; v1@482.507,-88.297 cw(c482.928,-88.408) 482.928,-87.973 ; v1@482.508,-88.291 cw(c484.408,-88.291) v1@483.065,-86.948 ; v1@482.511,-87.536 cw(c483.448,-88.473) 483.448,-87.148 ; v1@482.511,-87.501 ccw(c483.653,-86.36) 483.653,-87.973 ; 482.61,-127.915 481.34,-127.915 ; 482.628,-84.209 483.654,-83.183 ; 482.73,-126.892 cw(c481.906,-127.715) 483.023,-128.044 ; 482.846,-123.107 481.975,-123.978 480.959,-123.978 ; 482.846,-122.858 cw(c482.538,-123.414) 483.174,-123.414 ; 483.118,-83.719 483.118,-81.616 483.654,-81.08 ; 483.174,-127.868 483.174,-127.605 ; v1@483.263,-88.309 cw(c484.072,-89.118) 484.072,-87.973 ; v1@483.263,-87.547 cw(c484.225,-88.509) 484.225,-87.148 cw(c484.225,-85.787) v1@483.263,-86.749 ; v1@483.263,-87.511 ccw(c484.379,-86.396) 484.379,-87.973 ; v1@483.27,-87.528 cw(c484.926,-87.432) 483.753,-86.259 ; v1@483.37,-86.642 cw(c484.77,-88.042) 485.14,-86.097 ; 483.501,-122.858 ccw(c483.81,-123.414) 483.174,-123.414 ; 483.584,-80.332 cw(c485.023,-81.771) 485.023,-79.736 ; 483.603,-87.518 ccw(c483.603,-85.916) 485.001,-86.699 ; 483.631,-87.973 ccw(c483.631,-86.602) 484.998,-86.709 ; 483.924,-127.193 ccw(c483.924,-125.861) 484.866,-126.803 ; 483.946,-127.857 cw(c484.909,-127.386) 484.151,-126.628 ; 483.947,-122.276 ccw(c484.802,-122.602) 484.155,-123.249 ; 483.981,341.109 ccw(c483.235,341.855) 484.29,341.855 ccw(c485.345,341.855) 484.599,341.109 ; 483.981,343.031 cw(c483.235,342.285) 484.29,342.285 cw(c485.345,342.285) 484.599,343.031 ; 483.981,343.649 ccw(c483.235,344.395) 484.29,344.395 ccw(c485.345,344.395) 484.599,343.649 ; 484.103,323.118 cw(c484.103,321.624) 485.16,322.681 ; 484.128,323.796 ccw(c485.241,323.895) 485.241,322.777 ; 484.158,323.121 cw(c484.23,322.254) 484.844,322.869 cw(c485.261,323.286) 484.721,323.523 ; 484.164,323.121 cw(c484.262,322.033) 485.035,322.806 cw(c485.722,323.493) 484.767,323.67 ; 484.216,-87.518 v1(482.494,-87.518) ; 484.29,336.23 484.29,340.8 ; 484.29,337.46 ccw(c485.225,337.46) 484.564,336.799 ; 484.334,-87.973 ccw(c484.334,-86.657) 485.646,-86.76 ; 484.35,-86.658 cw(c482.928,-86.547) 482.928,-87.973 ; 484.353,-86.791 ccw(c483.753,-86.863) 483.753,-86.259 ; 484.405,336.115 484.405,340.685 484.29,340.8 ; 484.405,339.468 ccw(c482.958,339.468) 483.981,340.491 cw(c483.235,339.745) 484.29,339.745 cw(c485.345,339.745) 484.599,340.491 ccw(c485.068,340.022) 484.405,340.022 ; 484.434,-86.381 cw(c482.494,-85.294) v1(482.494,-87.518) ; 484.474,-86.319 cw(c482.864,-85.171) 482.864,-87.148 ; 484.53,-127.571 cw(c485.773,-126.963) 484.794,-125.985 ; 484.546,-87.188 ccw(c483.394,-88.341) 483.394,-86.711 ccw(c483.394,-85.081) 484.546,-86.234 ; 484.555,-122.508 ccw(c485.83,-122.994) 484.865,-123.959 ; 484.571,-86.259 483.753,-86.259 ; 484.58,323.316 cw(c485.732,322.164) 485.732,323.793 cw(c485.732,325.423) 484.58,324.271 ; 484.586,-87.148 482.864,-87.148 ; 484.599,-127.863 cw(c486.481,-127.849) 485.15,-126.518 ; 484.642,-127.026 485.15,-126.518 485.785,-126.518 486.319,-125.985 486.978,-125.985 ; 484.673,-87.288 cw(c484.296,-87.91) 485.023,-87.91 ; 484.683,-123.257 ccw(c483.924,-124.016) 483.924,-122.943 cw(c483.924,-125.243) 485.55,-123.616 ; 484.709,-80.308 cw(c483.548,-82.513) v1@486.039,-82.513 ; 484.749,323.598 cw(c485.698,323.31) 485.698,324.301 ; 484.775,323.854 ccw(c485.952,323.959) 485.952,322.777 ; 484.778,323.793 ccw(c486.543,323.793) 485.295,322.546 ; 484.88,-122.946 cw(c485.558,-122.268) 484.599,-122.268 ccw(c486.784,-122.268) 485.239,-123.813 ; 485.005,-79.729 cw(c484.043,-80.691) 485.404,-80.691 ; 485.011,-79.733 cw(c484.115,-81.436) 486.039,-81.436 ; 485.048,-86.714 cw(c485.799,-86.82) 485.799,-86.061 ; 485.063,322.777 486.46,321.38 486.46,318.205 486.866,317.799 486.866,317.266 ; 485.086,-80.383 cw(c485.196,-81.57) 486.039,-80.727 ; 485.206,-87.402 486.547,-86.061 ; 485.373,-87.288 ccw(c485.75,-87.91) 485.023,-87.91 ; 485.404,-82.26 ccw(c482.474,-82.26) 484.546,-80.188 cw(c483.394,-81.341) 485.023,-81.341 cw(c486.653,-81.341) 485.5,-80.188 ; 485.404,-80.092 485.404,-83.211 485.912,-83.719 488.6,-83.719 489.291,-84.41 489.291,-83.796 488.833,-83.338 486.293,-83.338 486.039,-83.084 v1@486.039,-82.322 ; 485.412,-86.159 ccw(c485.921,-85.436) 486.547,-86.061 ; 485.468,-84.163 489.044,-84.163 ; 485.561,-123.627 ccw(c486.978,-122.211) 486.978,-124.214 ; 485.648,-126.655 cw(c486.978,-127.985) 486.978,-126.104 ; 485.649,329.845 ccw(c483.999,331.496) 486.333,331.496 ; 485.658,-124.334 485.658,-124.232 483.694,-122.268 483.174,-122.268 ; 485.673,-86.061 486.547,-86.061 ; 485.692,-86.805 cw(c486.547,-86.925) 486.547,-86.061 ; 485.695,-79.774 ccw(c486.882,-79.884) 486.039,-80.727 ; 485.989,-126.314 cw(c486.686,-127.012) 486.956,-126.063 ; 486.159,314.984 cw(c484.453,313.277) 486.866,313.277 ; 486.159,315.585 ccw(c484.453,317.292) 486.866,317.292 ; 486.268,-124.334 484.202,-122.268 483.174,-122.268 ; 486.324,328.785 cw(c485.044,327.504) 486.855,327.504 cw(c488.665,327.504) 487.385,328.785 ; 486.324,329.845 ccw(c485.406,330.763) 486.705,330.763 ; 486.333,328.793 486.333,327.73 ; 486.333,330.756 ccw(c487.62,330.756) 486.71,329.845 ; 486.333,334.149 cw(c488.145,334.149) 486.864,335.431 ; 486.333,338.08 ccw(c488.145,338.08) 486.864,336.799 ; 486.333,338.545 cw(c489.084,338.545) 487.139,340.491 ccw(c488.187,339.443) 486.705,339.443 ; 486.333,340.115 cw(c487.515,340.115) 486.679,340.951 ; 486.333,341.085 cw(c489.084,341.085) 487.139,343.031 ccw(c487.885,342.285) 486.83,342.285 ccw(c485.775,342.285) 486.521,343.031 ; 486.333,341.421 ccw(c487.367,341.421) 486.69,340.639 ; 486.333,342.655 cw(c487.515,342.655) 486.679,343.491 ; 486.441,345.365 ccw(c485.691,346.115) 486.747,346.215 ; 486.509,349.462 cw(c485.648,348.601) 486.866,348.601 ; 486.521,340.491 cw(c486.077,340.047) 486.705,340.047 ; 486.521,341.109 ccw(c485.775,341.855) 486.83,341.855 ccw(c487.885,341.855) 487.139,341.109 ; 486.705,329.465 486.705,336.115 486.705,340.675 ; 486.705,331.488 ccw(c489.027,331.488) 487.385,329.845 ; 486.705,331.804 487.476,331.032 487.476,325.317 486.855,324.696 ; 486.83,340.8 486.83,343.34 486.333,342.843 ; 486.847,313.145 cw(c485.941,312.239) 487.222,312.239 ; 486.855,329.315 486.855,324.696 ; 486.857,313.136 cw(c486.342,312.423) 487.222,312.423 ; 486.866,349.656 486.866,347.746 486.866,345.79 486.206,345.129 484.809,345.129 484.29,344.61 484.29,343.34 484.29,340.8 ; 486.973,313.159 ccw(c487.292,312.955) 487.025,312.688 ; v1@486.978,-127.076 486.978,-125.985 ; v1@486.978,-126.727 ccw(c487.735,-126.727) v1@487.2,-127.262 ; 486.978,-124.453 cw(c486.978,-125.479) 487.704,-124.754 ; 486.999,328.785 cw(c485.849,327.634) 487.476,327.634 ; 486.999,329.845 ccw(c485.849,330.996) 487.476,330.996 ; 487.055,-83.338 v1@486.039,-82.322 ; 487.058,306.013 cw(c487.058,304.648) 488.024,305.614 ; 487.116,341.131 cw(c488.597,342.843) 486.333,342.843 ; 487.222,310.966 487.222,311.347 ; 487.465,-105.318 487.465,-101.941 ; 487.476,327.375 cw(c489.47,327.375) 488.06,328.785 ; 487.476,331.032 ccw(c488.963,331.032) 488.01,329.891 ; 487.984,310.611 487.247,311.347 487.222,311.347 ; 488,305.67 ccw(c487.65,305.664) 487.65,306.013 ; 488.119,305.544 487.65,306.013 ; 488.403,-86.386 ccw(c488.403,-85.211) 489.234,-86.042 ; v1(488.452,-128.11) 488.452,-124.74 488.046,-124.334 486.978,-124.334 ; 488.452,-125.502 487.284,-124.334 486.978,-124.334 ; 488.498,317.209 cw(c487.286,315.997) 489,315.997 ; 488.498,347.804 ccw(c487.31,348.992) 488.99,348.992 ; 488.517,345.485 489.37,344.633 489.37,343.34 ; 488.517,347.852 cw(c490.795,347.852) 489.184,349.462 ccw(c489.654,348.993) 488.99,348.993 ; 488.538,317.187 cw(c488.409,316.61) 489,316.61 ; 488.591,-84.163 cw(c488.591,-85.073) 489.234,-84.43 ; 488.637,313.206 cw(c489.88,313.262) 489,314.141 ; 488.637,317.266 cw(c489.721,317.266) 488.954,318.033 ; 488.745,-83.25 cw(c487.622,-84.372) 489.21,-84.372 ; 488.795,349.462 cw(c488.326,348.993) 488.99,348.993 ; 488.833,-86.061 489.291,-86.061 ; 488.845,335.431 cw(c486.94,333.525) 489.635,333.525 ; 488.845,336.799 ccw(c486.94,338.705) 489.635,338.705 ; 488.873,336.625 488.873,341.573 ; 488.873,337.501 ccw(c489.866,337.501) 489.164,336.799 ; 488.873,338.545 cw(c491.624,338.545) 489.679,340.491 ; 488.873,340.115 cw(c490.055,340.115) 489.219,340.951 ; 488.873,341.485 ccw(c490.055,341.485) 489.219,340.649 ; 488.873,341.505 cw(c490.706,341.505) 489.627,342.987 ; 488.873,343.055 ccw(c491.624,343.055) 489.679,341.109 ; 488.873,344.494 ccw(c489.616,344.494) 489.461,343.767 ; 489.005,335.365 cw(c489.005,333.571) 490.273,334.84 ; 489.005,338.863 cw(c491.307,338.863) 489.679,340.491 ; 489.005,340.435 489.005,336.115 489.005,332.933 489.635,332.302 ; 489.05,312.669 ccw(c489.697,313.316) 490.262,312.596 ; 489.061,340.491 cw(c487.675,339.105) 489.635,339.105 ; 489.061,341.109 ccw(c488.315,341.855) 489.37,341.855 ccw(c490.425,341.855) 489.679,341.109 ; 489.061,343.031 cw(c488.315,342.285) 489.37,342.285 cw(c490.425,342.285) 489.679,343.031 cw(c490.425,342.285) 490.425,343.34 cw(c490.425,344.395) 489.679,343.649 ; 489.061,343.649 ccw(c488.315,344.395) 489.37,344.395 ccw(c490.425,344.395) 489.679,343.649 ; 489.089,335.381 cw(c489.369,334.693) 489.894,335.219 ; 489.116,-101.941 v1(489.96,-101.941) ; 489.191,343.225 ccw(c490.59,344.127) 490.59,342.462 ; 489.199,340.927 cw(c490.487,339.967) 490.487,341.573 ; 489.205,322.982 cw(c491.103,321.084) 491.103,323.768 ; 489.212,-86.082 cw(c488.833,-85.998) 488.833,-86.386 486.801,-86.386 ; 489.215,340.654 ccw(c490.029,341.424) 490.029,340.303 ; 489.305,335.89 cw(c488.509,335.094) 489.635,335.094 ; 489.305,336.339 ccw(c488.509,337.136) 489.635,337.136 ; 489.396,322.411 cw(c491.103,320.704) 491.103,323.118 ; 489.458,312.262 488.517,313.202 ; 489.472,323.25 cw(c490.084,322.638) 490.656,323.287 ; 489.508,343.859 491.032,343.859 ; 489.569,312.151 ccw(c490.153,312.735) 490.663,312.085 ; 489.635,332.124 cw(c490.497,332.124) v1@490.153,332.915 ; 489.635,334.224 ccw(c491.43,334.224) v1@490.161,332.955 ; 489.635,335.477 490.143,334.969 490.143,325.571 491.103,324.611 491.103,323.793 ; 489.635,339.668 490.27,340.303 491.54,340.303 ; 489.635,340.535 489.635,332.302 ; 489.687,341.101 ccw(c491.54,342.855) 491.54,340.303 ; 489.72,340.539 cw(c491.783,339) 491.783,341.573 ; 489.737,343.577 ccw(c491.783,344.897) 491.783,342.462 ; 489.748,343.12 cw(c491.032,342.374) 491.032,343.859 ; 489.77,305.544 489.77,306.513 489,307.283 480.618,307.283 479.856,307.283 479.21,307.93 479.21,340.8 ; 489.962,323.739 cw(c490.543,323.158) 491.086,323.775 ; 490.18,323.196 ccw(c489.583,323.793) 490.428,323.793 ccw(c488.798,323.793) 489.951,324.946 ccw(c491.103,326.098) 491.103,324.468 ; 490.223,311.961 ccw(c489.498,311.236) 489.498,312.262 ccw(c489.498,313.288) 490.223,312.562 ; 490.498,323.494 ccw(c490.016,323.256) 490.016,323.793 ; 490.498,324.093 cw(c490.016,324.331) 490.016,323.793 ; 490.656,325.058 cw(c489.602,324.004) 491.078,323.797 ; 490.661,-84.456 491.144,-83.973 494.981,-83.973 495.387,-84.379 ; 490.719,-84.475 cw(c491.931,-85.687) 491.931,-83.973 ; 490.778,323.793 489,322.015 489,318.078 488.517,317.596 488.517,317.266 489,316.784 489,314.141 488.517,313.659 488.517,313.202 ; 490.824,311.961 cw(c491.55,311.236) 491.55,312.262 cw(c491.55,313.288) 490.824,312.562 ; 490.921,340.303 ccw(c490.921,341.527) 491.786,340.662 ; 490.981,-105.275 490.981,-101.941 ; 491.032,343.467 491.032,343.859 ; 491.173,341.192 cw(c491.173,340.325) 491.786,340.938 ; 491.228,342.97 ccw(c491.228,343.76) 491.786,343.202 ; 491.317,342.97 cw(c491.317,345.287) 489.679,343.649 ; 491.371,341.192 ccw(c491.371,338.798) 489.679,340.491 ; 491.413,343.467 491.413,348.431 ; 491.413,345.224 ccw(c493.532,345.224) 492.034,343.726 ; 491.783,341.573 488.873,341.573 ; 491.783,342.462 489.37,342.462 ; 491.909,341.192 489.762,341.192 489.37,340.8 ; 491.91,341.954 489.37,341.954 ; 491.91,342.97 489.739,342.97 489.37,343.34 ; 491.91,347.15 497.283,352.523 497.283,353.412 ; 491.91,348.039 491.91,343.34 ; 492.028,349.193 496.865,354.031 ; 492.079,-86.061 487.69,-86.061 ; 492.161,-85.98 489.373,-85.98 489.291,-86.061 ; 492.606,310.491 cw(c492.606,309.159) 493.548,310.101 ; 492.607,312.381 ccw(c492.621,313.188) 493.191,312.617 ; 492.638,310.498 cw(c492.865,309.967) 493.274,310.376 ; 492.663,312.242 cw(c493.569,311.337) 493.569,312.617 ; 492.682,312.27 cw(c493.191,312.071) 493.191,312.617 ; 494.265,309.385 ccw(c495.025,310.146) 495.657,309.274 ; 494.301,-83.973 cw(c494.301,-85.427) 495.33,-84.399 ; 494.45,-105.318 494.45,-101.941 ; 494.773,309.385 ccw(c495.284,309.897) 495.682,309.292 ; 494.803,308.846 ccw(c495.478,309.521) 496.038,308.748 ; 494.886,313.17 cw(c496.053,312.003) 496.053,313.653 ; 494.906,313.19 ccw(c493.768,314.328) 495.378,314.328 ; 495.159,310.141 493.508,310.141 ; 495.43,308.988 cw(c494.969,309.18) 494.969,308.68 ; 495.445,-84.399 cw(c496.094,-85.048) 496.094,-84.13 ; 495.467,308.392 ccw(c494.969,308.106) 494.969,308.68 ; 495.467,312.993 ccw(c494.977,313.482) 495.522,313.911 ; 495.477,308.68 494.461,309.696 494.461,309.95 ; v1@495.53,348.485 cw(c496.874,347.142) v1@496.874,349.041 ; 495.58,309.95 494.461,309.95 ; 495.585,310.478 cw(c494.339,309.232) 496.029,308.735 ; 495.637,-84.13 498.866,-84.13 ; 496.044,314.328 494.334,312.617 494.207,312.617 ; v1@496.048,349.13 ccw(c496.478,349.559) v1@496.858,349.086 ; 496.077,-84.13 cw(c496.077,-85.048) 496.727,-84.399 ; 496.103,355.154 cw(c498.652,352.605) 498.652,356.209 ccw(c498.652,354.58) 497.5,355.732 ccw(c496.347,356.884) 497.977,356.884 ; v1@496.128,348.285 cw(c496.508,347.812) v1@496.937,348.241 ; v1@496.13,348.287 cw(c496.939,347.478) v1@496.939,348.622 ; v1@496.13,349.085 cw(c498.121,347.094) 498.647,349.86 ; v1@496.136,348.298 cw(c496.556,348.187) 496.556,348.622 ; v1@496.137,348.304 cw(c498.037,348.304) v1@496.693,349.648 ; v1@496.14,349.059 cw(c497.077,348.122) 497.077,349.447 ; v1@496.14,349.095 ccw(c497.281,350.236) 497.281,348.622 ; 496.239,308.68 494.969,308.68 ; 496.257,352.386 497.283,353.412 ; 496.359,309.704 cw(c495.535,308.88) 496.652,308.551 ; 496.475,313.489 495.604,312.617 494.588,312.617 ; 496.475,313.738 cw(c496.166,313.181) 496.803,313.181 ; 496.551,-116.162 496.551,-112.743 496.551,-111.219 ; 496.747,352.876 496.747,354.979 497.283,355.515 ; 496.803,308.728 496.803,308.99 ; 496.842,-84.399 cw(c497.491,-85.048) 497.491,-84.13 ; v1@496.892,348.287 cw(c497.701,347.478) 497.701,348.622 ; v1@496.892,349.049 cw(c497.854,348.086) 497.854,349.447 cw(c497.854,350.809) v1@496.892,349.846 ; v1@496.892,349.084 ccw(c498.007,350.2) 498.007,348.622 ; v1@496.899,349.068 cw(c498.555,349.164) 497.382,350.336 ; v1@496.999,349.953 cw(c498.399,348.554) 498.769,350.498 ; 497.13,313.738 ccw(c497.439,313.181) 496.803,313.181 ; 497.213,356.263 cw(c498.652,354.824) 498.652,356.859 ; 497.232,349.077 ccw(c497.232,350.68) 498.63,349.897 ; 497.259,348.622 ccw(c497.259,349.994) 498.627,349.886 ; 497.474,-84.13 cw(c497.474,-85.048) 498.124,-84.399 ; 497.553,309.403 ccw(c497.553,310.735) 498.494,309.793 ; 497.575,308.739 cw(c498.537,309.21) 497.78,309.967 ; 497.576,314.319 ccw(c498.431,313.993) 497.784,313.347 ; 497.844,349.077 v1(496.122,349.077) ; 497.962,348.622 ccw(c497.962,349.939) 499.275,349.836 ; 497.979,349.937 cw(c496.556,350.049) 496.556,348.622 ; 497.982,349.804 ccw(c497.382,349.732) 497.382,350.336 ; 498.063,350.214 cw(c496.123,351.301) v1(496.122,349.077) ; 498.102,350.276 cw(c496.493,351.424) 496.493,349.447 ; 498.154,-114.487 499.893,-114.487 ; 498.159,309.025 cw(c499.401,309.633) 498.423,310.611 ; 498.175,349.407 ccw(c497.022,348.255) 497.022,349.884 ccw(c497.022,351.514) 498.175,350.362 ; 498.183,314.088 ccw(c499.458,313.602) 498.494,312.637 ; 498.2,350.336 497.382,350.336 ; 498.202,-114.439 498.202,-112.743 ; 498.202,-111.219 498.202,-109.765 ; 498.215,349.447 496.493,349.447 ; 498.228,308.733 cw(c500.11,308.747) 498.779,310.077 ; 498.239,-84.399 cw(c498.888,-85.048) 498.888,-84.13 ; 498.271,309.569 498.779,310.077 499.414,310.077 499.947,310.611 500.607,310.611 ; 498.302,349.307 cw(c497.925,348.686) 498.652,348.686 ; 498.312,313.338 ccw(c497.553,312.579) 497.553,313.653 cw(c497.553,311.353) 499.179,312.979 ; 498.337,356.287 cw(c497.177,354.083) v1@499.668,354.083 ; 498.509,313.65 cw(c499.187,314.328) 498.228,314.328 ccw(c500.413,314.328) 498.868,312.783 ; 498.634,356.867 cw(c497.672,355.904) 499.033,355.904 ; 498.64,356.862 cw(c497.744,355.16) 499.668,355.16 ; 498.677,349.881 cw(c499.428,349.775) 499.428,350.534 ; 498.715,356.212 cw(c498.825,355.026) 499.668,355.869 ; 498.835,349.193 500.176,350.534 ; 499.002,349.307 ccw(c499.379,348.686) 498.652,348.686 ; 499.033,354.335 ccw(c496.102,354.335) 498.175,356.407 cw(c497.022,355.255) 498.652,355.255 cw(c500.281,355.255) 499.129,356.407 ; 499.033,356.503 499.033,353.384 499.541,352.876 502.229,352.876 502.92,352.185 502.92,352.799 502.462,353.257 499.922,353.257 499.668,353.511 v1@499.668,354.273 ; 499.041,350.436 ccw(c499.55,351.16) 500.176,350.534 ; 499.096,352.432 502.673,352.432 ; 499.19,312.968 ccw(c500.607,314.385) 500.607,312.381 ; 499.277,309.94 cw(c500.607,308.61) 500.607,310.491 ; 499.287,312.262 499.287,312.363 497.322,314.328 496.803,314.328 ; 499.302,350.534 500.176,350.534 ; 499.303,-114.487 cw(c499.303,-115.222) 499.824,-114.702 ; 499.32,349.791 cw(c500.176,349.67) 500.176,350.534 ; 499.324,356.822 ccw(c500.51,356.711) 499.668,355.869 ; 499.618,310.281 cw(c500.315,309.583) 500.585,310.533 ; 499.744,-104.438 cw(c498.781,-105.401) 500.143,-105.401 cw(c501.505,-105.401) 500.542,-104.438 ; 499.824,-114.354 ccw(c499.082,-113.612) 500.131,-113.612 ; 499.85,-107.907 cw(c499.23,-108.526) 500.107,-108.526 ; 499.896,312.262 497.83,314.328 496.803,314.328 ; 500.107,-119.095 cw(c502.115,-119.095) 501.104,-117.359 ; 500.107,-118.909 500.107,-117.933 500.948,-117.091 ; 500.107,-118.281 cw(c500.987,-118.281) 500.958,-117.401 ; 500.107,-117.964 cw(c501.456,-117.964) 500.777,-116.798 ; 500.107,-117.61 cw(c500.965,-117.61) 500.937,-116.752 ; 500.107,-109.765 500.107,-107.65 ; 500.107,-108.738 cw(c501.282,-108.738) 500.451,-107.907 ; 500.131,-114.459 v1(500.131,-112.04) 500.131,-111.202 ; v1(500.143,-105.556) 500.143,-103.658 ; v1@500.607,309.519 500.607,310.611 ; v1@500.607,309.868 ccw(c501.364,309.868) v1@500.829,309.333 ; 500.607,312.142 cw(c500.607,311.116) 501.333,311.842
